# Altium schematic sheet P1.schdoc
size 420 x 297 mm; Symbol: Drawing-Symbol_A4; @Project Name: Mini Piano PCB; @Page Count: 1; @Update Date: 2026-10-19; @Create Date: 2026-10-19; @Schematic Name: Schematic1; @Page No: 1; @Page Name: P1; Company: EasyEDA.com; Version: V1.0; Page Size: A4; Device: Drawing-Symbol_A4; @Create Time: 11:32:39; @Update Time: 11:32:39; Border: 1; Width: 1655; Height: 1170; Region Start: 1; X Region Count: 6; Y Region Count: 4; Blade Width: 10; Title Block Position: 3; @Board Name: Board1
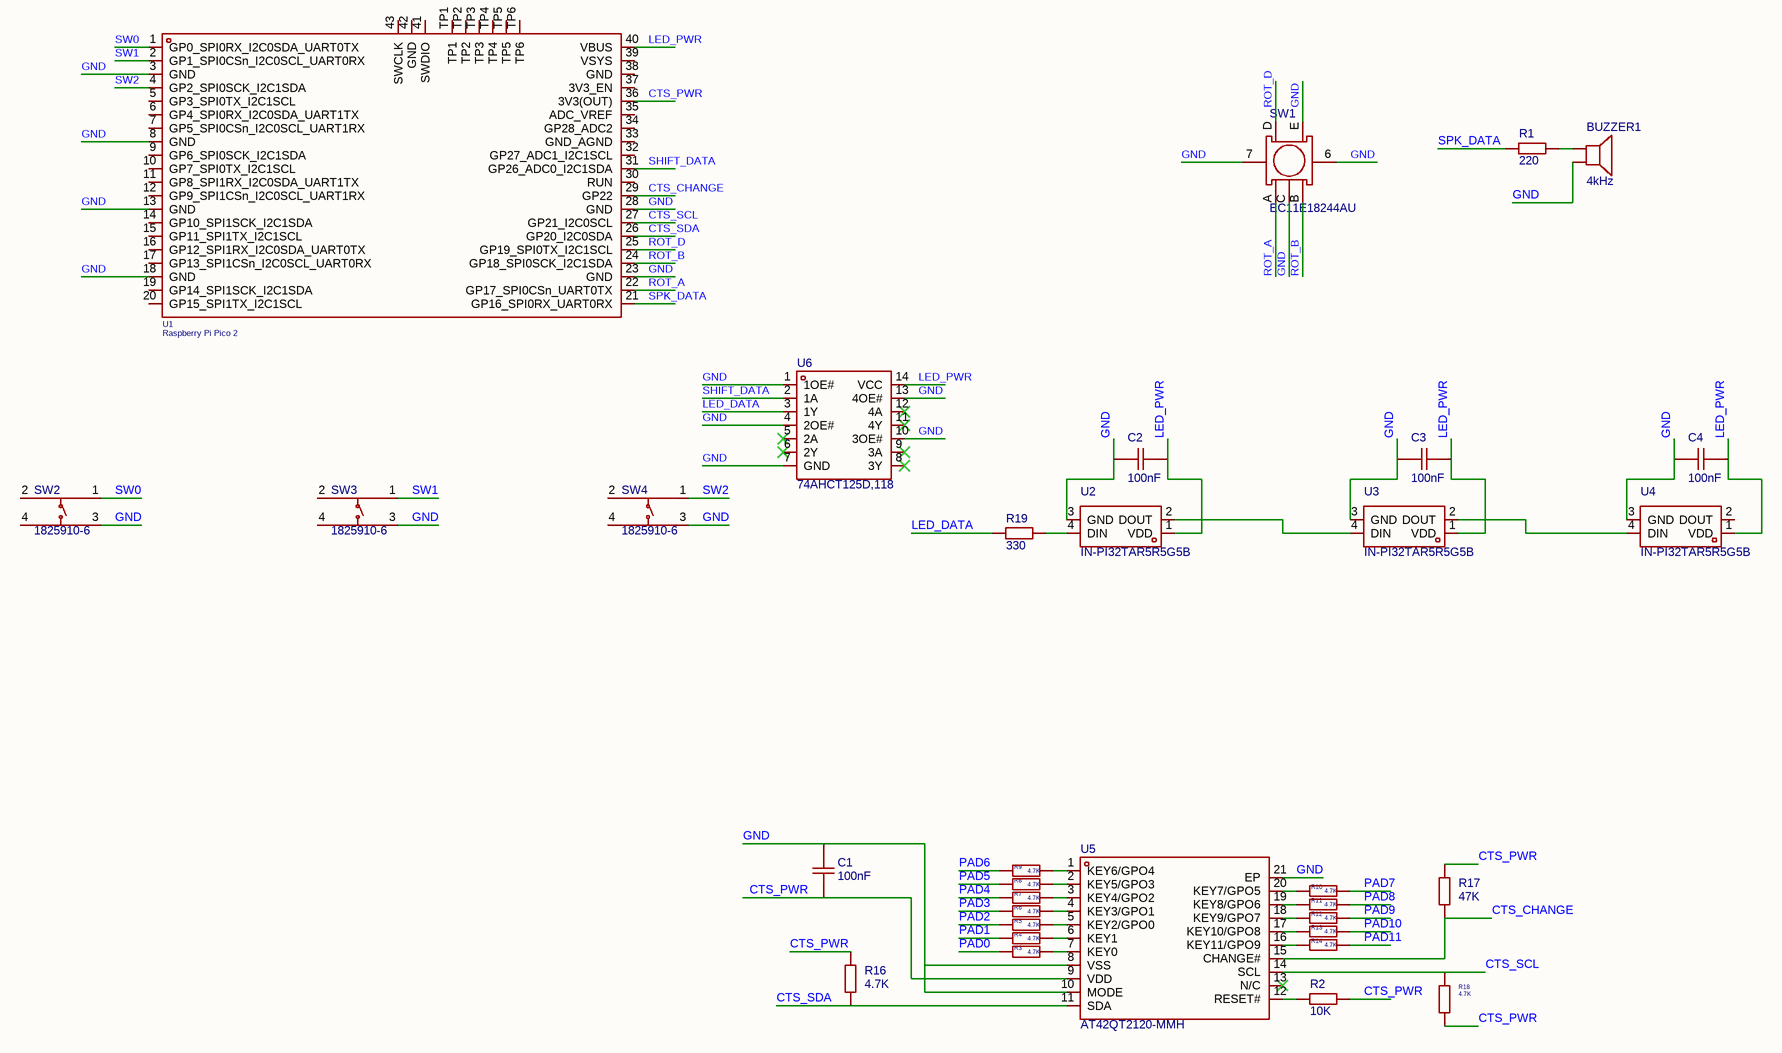
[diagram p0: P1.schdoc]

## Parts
BUZZER1  4kHz  [BUZ-TH_BD12.5-P5.00-D0.9]
C1  100nF  [C0603]
C2  100nF  [C0603]
C3  100nF  [C0603]
C4  100nF  [C0603]
R1  220  [R0603]
R2  10K  [R0603]
R3  4.7K  [R0603]
R4  4.7K  [R0603]
R5  4.7K  [R0603]
R6  4.7K  [R0603]
R7  4.7K  [R0603]
R8  4.7K  [R0603]
R9  4.7K  [R0603]
R10  4.7K  [R0603]
R11  4.7K  [R0603]
R12  4.7K  [R0603]
R13  4.7K  [R0603]
R14  4.7K  [R0603]
R16  4.7K  [R0603]
R17  47K  [R0603]
R18  4.7K  [R0603]
R19  330  [R0603]
SW1  EC11E18244AU  [SW-TH_EC11XXXXXXXX]
SW2  1825910-6  [SW-TH_4P-L6.0-W6.0-P4.50-LS6.5]
SW3  1825910-6  [SW-TH_4P-L6.0-W6.0-P4.50-LS6.5]
SW4  1825910-6  [SW-TH_4P-L6.0-W6.0-P4.50-LS6.5]
U1  Raspberry Pi Pico 2  [COMM-SMD_L51.0-W21.0-P2.54_SC0916]
U2  IN-PI32TAR5R5G5B  [LED-SMD_IN-PI32TARXRXGXB]
U3  IN-PI32TAR5R5G5B  [LED-SMD_IN-PI32TARXRXGXB]
U4  IN-PI32TAR5R5G5B  [LED-SMD_IN-PI32TARXRXGXB]
U5  AT42QT2120-MMH  [VQFN-20_L3.0-W3.0-P0.45-TL-EP]
U6  74AHCT125D,118  [SOP-14_L8.6-W3.9-P1.27-LS6.0-BL]

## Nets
CTS_CHANGE: R17.1 U1.29(GP22) U5.15(CHANGE#)
CTS_PWR: C1.2 R2.2 R16.2 R17.2 R18.1 U1.36(3V3(OUT)) U5.9(VDD)
CTS_SCL: R18.2 U1.27(GP21_I2C0SCL) U5.14(SCL)
CTS_SDA: R16.1 U1.26(GP20_I2C0SDA) U5.11(SDA)
GND: BUZZER1.2 C1.1 C2.2 C3.2 C4.2 SW1.6 SW1.7 SW1.C SW1.E SW2.3 SW3.3 SW4.3 U1.3(GND) U1.8(GND) U1.13(GND) U1.18(GND) U1.23(GND) U1.28(GND) U2.3(GND) U3.3(GND) U4.3(GND) U5.8(VSS) U5.10(MODE) U5.21(EP) U6.1(1OE#) U6.4(2OE#) U6.7(GND) U6.10(3OE#) U6.13(4OE#)
LED_DATA: R19.1 U6.3(1Y)
LED_PWR: C2.1 C3.1 C4.1 U1.40(VBUS) U2.1(VDD) U3.1(VDD) U4.1(VDD) U6.14(VCC)
PAD0: R3.1
PAD1: R4.1
PAD2: R5.1
PAD3: R6.1
PAD4: R7.1
PAD5: R8.1
PAD6: R9.1
PAD7: R10.2
PAD8: R11.2
PAD9: R12.2
PAD10: R13.2
PAD11: R14.2
ROT_A: SW1.A U1.22(GP17_SPI0CSn_UART0TX)
ROT_B: SW1.B U1.24(GP18_SPI0SCK_I2C1SDA)
ROT_D: SW1.D U1.25(GP19_SPI0TX_I2C1SCL)
SHIFT_DATA: U1.31(GP26_ADC0_I2C1SDA) U6.2(1A)
SPK_DATA: R1.1 U1.21(GP16_SPI0RX_UART0RX)
SW0: SW2.1 U1.1(GP0_SPI0RX_I2C0SDA_UART0TX)
SW1: SW3.1 U1.2(GP1_SPI0CSn_I2C0SCL_UART0RX)
SW2: SW4.1 U1.4(GP2_SPI0SCK_I2C1SDA)
NetBUZZER1_1: BUZZER1.1 R1.2
NetR2_1: R2.1 U5.12(RESET#)
NetR3_2: R3.2 U5.7(KEY0)
NetR4_2: R4.2 U5.6(KEY1)
NetR5_2: R5.2 U5.5(KEY2/GPO0)
NetR6_2: R6.2 U5.4(KEY3/GPO1)
NetR7_2: R7.2 U5.3(KEY4/GPO2)
NetR8_2: R8.2 U5.2(KEY5/GPO3)
NetR9_2: R9.2 U5.1(KEY6/GPO4)
NetR10_1: R10.1 U5.20(KEY7/GPO5)
NetR11_1: R11.1 U5.19(KEY8/GPO6)
NetR12_1: R12.1 U5.18(KEY9/GPO7)
NetR13_1: R13.1 U5.17(KEY10/GPO8)
NetR14_1: R14.1 U5.16(KEY11/GPO9)
NetR19_2: R19.2 U2.4(DIN)
NetU2_2: U2.2(DOUT) U3.4(DIN)
NetU3_2: U3.2(DOUT) U4.4(DIN)

Not connected (* = marked no-connect by the designer): SW2 2 4; SW3 2 4; SW4 2 4; U1 5(GP3_SPI0TX_I2C1SCL) 6(GP4_SPI0RX_I2C0SDA_UART1TX) 7(GP5_SPI0CSn_I2C0SCL_UART1RX) 9(GP6_SPI0SCK_I2C1SDA) 10(GP7_SPI0TX_I2C1SCL) 11(GP8_SPI1RX_I2C0SDA_UART1TX) 12(GP9_SPI1CSn_I2C0SCL_UART1RX) 14(GP10_SPI1SCK_I2C1SDA) 15(GP11_SPI1TX_I2C1SCL) 16(GP12_SPI1RX_I2C0SDA_UART0TX) 17(GP13_SPI1CSn_I2C0SCL_UART0RX) 19(GP14_SPI1SCK_I2C1SDA) 20(GP15_SPI1TX_I2C1SCL) 30(RUN) 32(GP27_ADC1_I2C1SCL) 33(GND_AGND) 34(GP28_ADC2) 35(ADC_VREF) 37(3V3_EN) 38(GND) 39(VSYS) 41(SWDIO) 42(GND) 43(SWCLK) TP1 TP2 TP3 TP4 TP5 TP6; U4 2(DOUT); U5 13(N/C)*; U6 5(2A)* 6(2Y)* 8(3Y)* 9(3A)* 11(4Y)* 12(4A)*

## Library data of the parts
BUZZER1 = PS1240P02BT: Driver Circuitry:Passive (Externally Driven) Technology:Piezoelectric Voltage Rating:3V Voltage - Supply:30V Voltage - Supply:30V Frequency:4kHz Current Consumption:- Sound Pressure Level(SPL):70dB Diameter(φD):12.2mm Length:- Width:- Height:7.8mm Operati; Manufacturer: TDK; AddInBom: yes; ModelId: ecf4a8af60cd4e66827ceae195775fa10819f05c4eef4c71ace90d822a990e87; ModelName: BUZ-TH_D12.5-H7.0-P5.0; ModelTransform: 492.125,492.08189,0,90,0,0,0,0,-177.165; Voltage Rating: 3V; Voltage - Supply: 30V; Sound Pressure Level(SPL): 70dB
C1-C4 = CAP_0603: Symbol: CAP_OLD; ConvertToPcb: yes; ModelId: 624118aa3cc7497086c383c2d72e08520819f05c4eef4c71ace90d822a990e87; ModelName: C0603_L1.6-W0.8-H0.8; ModelTransform: 62.992,31.496,0,0,0,0,0,0,0
R1-R14 R16-R19 = Res_0603: Symbol: Res; ConvertToPcb: yes; ModelId: 112863783b5b41f1b5254f87eedc79320819f05c4eef4c71ace90d822a990e87; ModelTransform: 31.8897,63.7794,0,90,0,0,0,0,0
SW1 = EC11E18244AU: Encoder Type:Incremental Number of Detents / Pulses (Incremental):36/18 Output Form:Two-phase output Mounting Type:Straight Current Rating (Max):10mA Rated Voltage (Max):5V Operating Temperature:-40℃~+85℃ Operating Temperature:-40℃~+85℃; Manufacturer: ALPSALPINE(阿尔卑斯阿尔派); AddInBom: yes; ModelId: 34d0052b40b94bce9e3816cf478199620819f05c4eef4c71ace90d822a990e87; ModelName: SW-TH_EC11XXXXXXXX-L11.7-W12.0-H24.5-P2.5-LS14.5; ModelTransform: 495.18696,578.739,0,0,0,0,0,0,-137.795; Number of Detents / Pulses (Incremental): 36/18; Current Rating (Max): 10mA; Rated Voltage (Max): 5V
SW2-SW4 = 1825910-6: Circuit:SPST Actuator Style:Round Button Operating Force:1.6N Mounting Type:Through Hole Length:6mm Width:6mm Switch Height:5mm Contact Current:50mA Voltage Rating:24V With Lamp:- Termination Style:PC Pin Life:- Operating Temperature:-35℃~+85℃ Operating T; Manufacturer: TE Connectivity(泰科电子); AddInBom: yes; ModelId: 1b2aa19db9484d8f9f922c35047145250819f05c4eef4c71ace90d822a990e87; ModelName: SW-TH_4P-L6.0-W6.0-H5.0-LS6.5-P4.50; ModelTransform: 236.22,323.03,0,90,0,0,0,0,-137.795; Circuit: SPST; Operating Force: 1.6N; Switch Height: 5mm; Contact Current: 50mA; Voltage Rating: 24V
U1 = Raspberry Pi Pico 2: Manufacturer: Raspberry Pi(树莓派); Symbol: PICO 2; AddInBom: yes
U2-U4 = IN-PI32TAR5R5G5B: Edited to fix pad spacing error; Manufacturer: Inolux; Add into BOM: yes; 3D Model: 75ef59b847fb49fcb710bd841028373d0819f05c4eef4c71ace90d822a990e87; 3D Model Transform: 231.496,114.567,0,180,0,0,0,0,-35.433
U5 = AT42QT2120-MMH: Number of Channels:12 Features:Waterproof anti-interference touch；Automatic sensitivity calibration；Capacitive Touch；Sliding touch；Proximity detection Whether the Lock:- Voltage - Supply:1.8V~5.5V Voltage - Supply:1.8V~5.5V Current - Supply:- Operating Te; Manufacturer: MICROCHIP(美国微芯); AddInBom: yes; ModelId: 88687782d772487c864767ae6bef615b0819f05c4eef4c71ace90d822a990e87; ModelName: VQFN-20_L3.0-W3.0-H0.8-P0.45-TL-EP; ModelTransform: 118.11,118.11,0,0,0,0,0,-0.002,0; Number of Channels: 12
U6 = 74AHCT125D,118: Input type:Schmitt trigger output type:Tri-State Voltage - Supply:4.5V~5.5V Voltage - Supply:4.5V~5.5V Number of Elements:4 Number of Bits per Element:1 Channel Type:Unidirectional Current - Output Low(IOL):8mA Current - Output High(IOH):8mA Logic Family:; Manufacturer: Nexperia(安世); AddInBom: yes; ModelId: 4e45eb17859b4142a1a301d6ba2648950819f05c4eef4c71ace90d822a990e87; ModelTransform: 339.763,236.22,0,0,0,0,0,0,0; Number of Elements: 4; Number of Bits per Element: 1; Current - Output Low(IOL): 8mA; Logic Family: 74AHCT; Quiescent Current: 40uA; Propagation Delay: 4.3ns@5V,50pF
